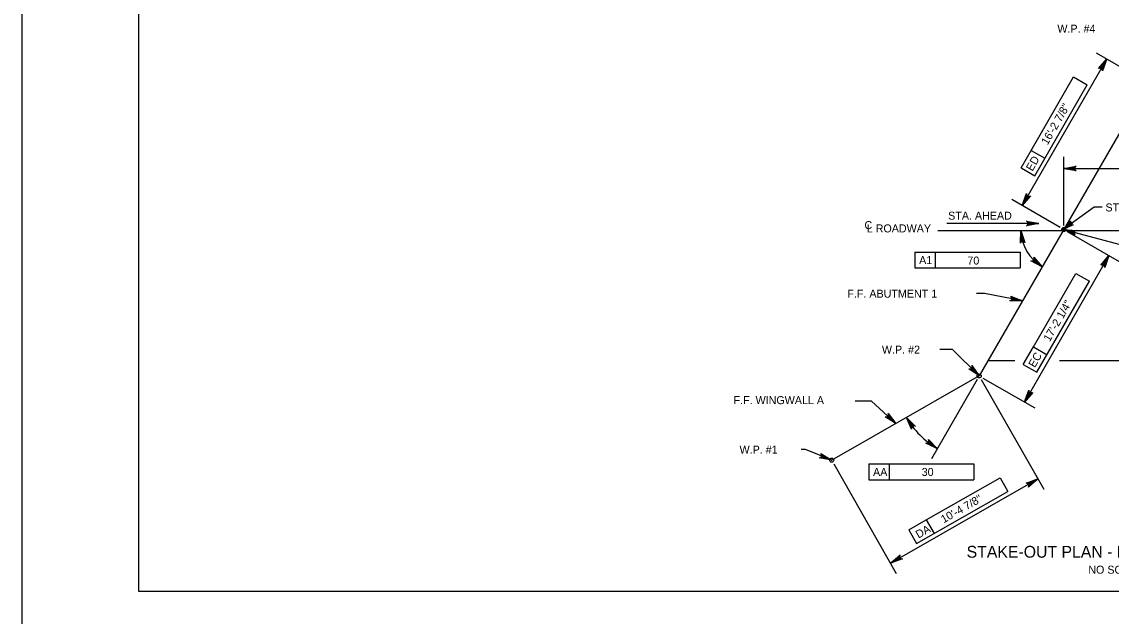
# Model space of a CAD drawing. Extents: x 179 to 454, y -271 to 54.
# Drawn here: x 209.75 to 226.08, y -87.62 to -78.72 of the extents above; entities that cross this region are included whole.
import ezdxf

# ---------------------------------------------------------------- set-up
doc = ezdxf.new("R2010")
doc.units = 0
for name, color, linetype in [('Level 1', 7, 'Continuous'), ('Level 2', 7, 'Continuous'), ('Level 3', 7, 'Continuous'), ('Level 4', 7, 'Continuous'), ('Level 41', 7, 'Continuous'), ('Level 5', 7, 'Continuous'), ('Level 63', 7, 'Continuous')]:
    doc.layers.add(name, color=color, linetype=linetype)

msp = doc.modelspace()

# ---------------------------------------------------------------- linework, layer by layer
at = {"layer": 'Level 1'}
msp.add_lwpolyline([(211.497, -87.25), (242.997, -87.25), (242.997, -66.75), (211.497, -66.75)], close=True, dxfattribs=at)
at = {"layer": 'Level 2'}
for p, q in [((226.635, -79.633), (224.1, -84.024)), ((224.232, -83.795), (224.633, -83.795)), ((225.306, -83.795), (230.928, -83.795)), ((224.1, -84.024), (221.889, -85.286))]:
    msp.add_line(p, q, dxfattribs=at)
at = {"layer": 'Level 3'}
msp.add_line((223.48, -81.844), (229.019, -81.844), dxfattribs=at)
for centre in [(225.368, -81.829), (224.1, -84.024), (221.889, -85.286)]:
    msp.add_circle(centre, 0.0304, dxfattribs=at)
at = {"layer": 'Level 4'}
for p, q in [((226.582, -79.603), (225.859, -79.185)), ((226.012, -79.274), (224.745, -81.469)), ((224.878, -80.643), (225.514, -79.541)), ((224.932, -81.023), (225.719, -79.659)), ((225.514, -79.541), (225.719, -79.659)), ((224.727, -80.904), (224.878, -80.643)), ((224.878, -80.643), (225.083, -80.761)), ((225.368, -81.767), (225.369, -80.739)), ((224.727, -80.904), (224.932, -81.023)), ((225.369, -80.916), (232.059, -80.916)), ((225.314, -81.798), (224.591, -81.38)), ((225.339, -81.84), (225.825, -81.492)), ((225.825, -81.492), (225.945, -81.492)), ((224.996, -81.737), (223.615, -81.737)), ((225.421, -81.859), (226.2, -82.309)), ((223.137, -82.17), (223.44, -82.17)), ((223.137, -82.17), (223.137, -82.406)), ((223.44, -82.17), (223.44, -82.406)), ((223.44, -82.17), (224.712, -82.17)), ((224.712, -82.17), (224.712, -82.406)), ((226.046, -82.221), (224.779, -84.416)), ((223.137, -82.406), (224.712, -82.406)), ((224.912, -83.589), (225.548, -82.487)), ((224.966, -83.969), (225.753, -82.605)), ((225.548, -82.487), (225.753, -82.605)), ((224.178, -82.791), (224.058, -82.791)), ((224.751, -82.897), (224.178, -82.791)), ((224.761, -83.851), (224.912, -83.589)), ((224.912, -83.589), (225.117, -83.707)), ((224.761, -83.851), (224.966, -83.969)), ((224.069, -84.077), (223.384, -85.264)), ((224.131, -84.077), (225.069, -85.721)), ((224.153, -84.055), (224.932, -84.504)), ((221.919, -85.339), (222.857, -86.983)), ((222.447, -85.343), (222.749, -85.343)), ((222.447, -85.343), (222.447, -85.579)), ((222.749, -85.343), (222.749, -85.579)), ((222.749, -85.343), (224.022, -85.343)), ((224.022, -85.343), (224.022, -85.579)), ((222.447, -85.579), (224.022, -85.579)), ((222.77, -86.829), (224.981, -85.567)), ((223.307, -86.18), (224.412, -85.55)), ((224.412, -85.55), (224.529, -85.755)), ((223.161, -86.535), (224.529, -85.755)), ((223.044, -86.33), (223.307, -86.18)), ((223.307, -86.18), (223.424, -86.385)), ((223.044, -86.33), (223.161, -86.535))]:
    msp.add_line(p, q, dxfattribs=at)
for points in [[(225.936, -79.366), (225.97, -79.386), (226.012, -79.274)], [(225.487, -80.897), (225.487, -80.936), (225.369, -80.916)], [(224.787, -81.357), (224.821, -81.377), (224.745, -81.469)], [(225.5, -81.749), (225.477, -81.717), (225.391, -81.803)], [(225.368, -81.829), (225.479, -81.869), (225.484, -81.85)], [(225.97, -82.313), (226.004, -82.333), (226.046, -82.221)], [(224.1, -84.024), (224.023, -83.934), (224.009, -83.948)], [(224.821, -84.304), (224.855, -84.323), (224.779, -84.416)], [(222.85, -84.737), (222.769, -84.651), (222.756, -84.665)], [(223.057, -84.756), (223.09, -84.735), (223.011, -84.646)], [(223.384, -85.03), (223.363, -85.063), (223.473, -85.11)], [(221.889, -85.286), (221.783, -85.233), (221.775, -85.251)], [(224.869, -85.609), (224.888, -85.643), (224.981, -85.567)], [(222.862, -86.754), (222.882, -86.788), (222.77, -86.829)]]:
    msp.add_lwpolyline(points, close=True, dxfattribs=at)
for points in [[(224.996, -81.737), (224.81, -81.772), (224.824, -81.762), (224.831, -81.75), (224.834, -81.737), (224.831, -81.725), (224.824, -81.712), (224.81, -81.703), (224.996, -81.737), (224.824, -81.712), (224.831, -81.725), (224.996, -81.737), (224.834, -81.737), (224.831, -81.75), (224.996, -81.737), (224.824, -81.762)], [(224.723, -81.843), (224.786, -82.022), (224.774, -82.009), (224.761, -82.004), (224.748, -82.004), (224.736, -82.008), (224.725, -82.017), (224.717, -82.033), (224.723, -81.843), (224.725, -82.017), (224.736, -82.008), (224.723, -81.843), (224.748, -82.004), (224.761, -82.004), (224.723, -81.843), (224.774, -82.009)], [(225.368, -81.829), (226.44, -82.114), (226.531, -82.114)], [(225.045, -82.387), (224.876, -82.301), (224.894, -82.302), (224.907, -82.296), (224.917, -82.287), (224.923, -82.276), (224.924, -82.262), (224.919, -82.245), (225.045, -82.387), (224.924, -82.262), (224.923, -82.276), (225.045, -82.387), (224.917, -82.287), (224.907, -82.296), (225.045, -82.387), (224.894, -82.302)], [(226.046, -82.221), (225.983, -82.399), (225.982, -82.382), (225.975, -82.369), (225.965, -82.361), (225.953, -82.357), (225.939, -82.357), (225.923, -82.364), (226.046, -82.221), (225.939, -82.357), (225.953, -82.357), (226.046, -82.221), (225.965, -82.361), (225.975, -82.369), (226.046, -82.221), (225.982, -82.382)], [(224.751, -82.897), (224.561, -82.897), (224.577, -82.89), (224.587, -82.879), (224.591, -82.867), (224.591, -82.855), (224.586, -82.841), (224.574, -82.829), (224.751, -82.897), (224.586, -82.841), (224.591, -82.855), (224.751, -82.897), (224.591, -82.867), (224.587, -82.879), (224.751, -82.897), (224.577, -82.89)], [(224.1, -84.024), (223.701, -83.63), (223.512, -83.63)], [(224.1, -84.024), (223.943, -83.918), (223.96, -83.921), (223.974, -83.917), (223.985, -83.91), (223.992, -83.899), (223.995, -83.885), (223.992, -83.868), (224.1, -84.024), (223.995, -83.885), (223.992, -83.899), (224.1, -84.024), (223.985, -83.91), (223.974, -83.917), (224.1, -84.024), (223.96, -83.921)], [(224.779, -84.416), (224.842, -84.237), (224.843, -84.254), (224.85, -84.267), (224.86, -84.275), (224.872, -84.279), (224.887, -84.279), (224.902, -84.272), (224.779, -84.416), (224.887, -84.279), (224.872, -84.279), (224.779, -84.416), (224.86, -84.275), (224.85, -84.267), (224.779, -84.416), (224.843, -84.254)], [(222.85, -84.737), (222.484, -84.404)], [(222.85, -84.737), (222.688, -84.638), (222.706, -84.64), (222.72, -84.636), (222.73, -84.628), (222.736, -84.617), (222.739, -84.603), (222.736, -84.586), (222.85, -84.737), (222.739, -84.603), (222.736, -84.617), (222.85, -84.737), (222.73, -84.628), (222.72, -84.636), (222.85, -84.737), (222.706, -84.64)], [(223.011, -84.646), (223.144, -84.78), (223.128, -84.774), (223.114, -84.775), (223.102, -84.78), (223.093, -84.789), (223.087, -84.802), (223.087, -84.82), (223.011, -84.646), (223.087, -84.802), (223.093, -84.789), (223.011, -84.646), (223.102, -84.78), (223.114, -84.775), (223.011, -84.646), (223.128, -84.774)], [(223.472, -85.112), (223.3, -85.032), (223.317, -85.033), (223.331, -85.027), (223.34, -85.018), (223.345, -85.006), (223.346, -84.992), (223.34, -84.975), (223.472, -85.112), (223.346, -84.992), (223.345, -85.006), (223.472, -85.112), (223.34, -85.018), (223.331, -85.027), (223.472, -85.112), (223.317, -85.033)], [(221.889, -85.286), (221.495, -85.129), (221.43, -85.129)], [(221.889, -85.286), (221.703, -85.249), (221.72, -85.245), (221.731, -85.237), (221.738, -85.226), (221.74, -85.213), (221.738, -85.199), (221.728, -85.184), (221.889, -85.286), (221.738, -85.199), (221.74, -85.213), (221.889, -85.286), (221.738, -85.226), (221.731, -85.237), (221.889, -85.286), (221.72, -85.245)], [(224.981, -85.567), (224.837, -85.69), (224.844, -85.674), (224.844, -85.66), (224.84, -85.648), (224.832, -85.638), (224.819, -85.631), (224.802, -85.629), (224.981, -85.567), (224.819, -85.631), (224.832, -85.638), (224.981, -85.567), (224.84, -85.648), (224.844, -85.66), (224.981, -85.567), (224.844, -85.674)], [(222.77, -86.829), (222.914, -86.707), (222.907, -86.722), (222.906, -86.737), (222.911, -86.749), (222.919, -86.759), (222.931, -86.766), (222.949, -86.767), (222.77, -86.829), (222.931, -86.766), (222.919, -86.759), (222.77, -86.829), (222.911, -86.749), (222.906, -86.737), (222.77, -86.829), (222.907, -86.722)]]:
    msp.add_lwpolyline(points, dxfattribs=at)
for centre, radius, start, end in [((225.368, -81.829), 0.644, 181.3505, 240), ((224.1, -84.024), 1.255, 209.7121, 239.9991)]:
    msp.add_arc(centre, radius, start, end, dxfattribs=at)
at = {"layer": 'Level 5'}
msp.add_line((222.484, -84.404), (222.243, -84.404), dxfattribs=at)
for points in [[(226.012, -79.274), (225.949, -79.453), (225.948, -79.435), (225.941, -79.423), (225.931, -79.415), (225.919, -79.41), (225.904, -79.41), (225.889, -79.418), (226.012, -79.274), (225.904, -79.41), (225.919, -79.41), (226.012, -79.274), (225.931, -79.415), (225.941, -79.423), (226.012, -79.274), (225.948, -79.435)], [(225.369, -80.916), (225.555, -80.882), (225.541, -80.891), (225.534, -80.904), (225.532, -80.916), (225.534, -80.929), (225.541, -80.941), (225.555, -80.951), (225.369, -80.916), (225.541, -80.941), (225.534, -80.929), (225.369, -80.916), (225.532, -80.916), (225.534, -80.904), (225.369, -80.916), (225.541, -80.891)], [(224.745, -81.469), (224.808, -81.29), (224.809, -81.308), (224.816, -81.32), (224.826, -81.328), (224.838, -81.333), (224.852, -81.333), (224.868, -81.325), (224.745, -81.469), (224.852, -81.333), (224.838, -81.333), (224.745, -81.469), (224.826, -81.328), (224.816, -81.32), (224.745, -81.469), (224.809, -81.308)], [(225.339, -81.84), (225.471, -81.703), (225.465, -81.719), (225.466, -81.734), (225.471, -81.745), (225.481, -81.754), (225.494, -81.76), (225.511, -81.76), (225.339, -81.84), (225.494, -81.76), (225.481, -81.754), (225.339, -81.84), (225.471, -81.745), (225.466, -81.734), (225.339, -81.84), (225.465, -81.719)], [(225.368, -81.829), (225.557, -81.843), (225.54, -81.849), (225.53, -81.859), (225.525, -81.87), (225.523, -81.883), (225.527, -81.897), (225.539, -81.91), (225.368, -81.829), (225.527, -81.897), (225.523, -81.883), (225.368, -81.829), (225.525, -81.87), (225.53, -81.859), (225.368, -81.829), (225.54, -81.849)]]:
    msp.add_lwpolyline(points, dxfattribs=at)
at = {"layer": 'Level 63'}
msp.add_lwpolyline([(209.747, -88), (243.747, -88), (243.747, -66), (209.747, -66)], close=True, dxfattribs=at)

# ---------------------------------------------------------------- texts
at = {"layer": 'Level 4'}
for s, height, p in [('W.P. #4', 0.12, (225.272, -78.88)), ('STA.', 0.12, (225.993, -81.559)), ('STA. AHEAD', 0.12, (223.635, -81.682)), ('C', 0.12, (222.38, -81.824)), ('L ROADWAY', 0.12, (222.415, -81.873)), ('A1', 0.12, (223.2, -82.348)), ('F.F. ABUTMENT 1', 0.12, (222.124, -82.851)), ('W.P. #2', 0.12, (222.642, -83.69)), ('F.F. WINGWALL A', 0.12, (220.418, -84.447)), ('W.P. #1', 0.12, (220.508, -85.189)), ('AA', 0.12, (222.509, -85.524)), ('STAKE-OUT PLAN - LEFT SKEW', 0.17717, (223.912, -86.748)), ('NO SCALE', 0.12, (225.736, -86.988))]:
    msp.add_text(s, height=height, dxfattribs=at).set_placement(p)
for s, rotation, p in [('ED', 60, (224.898, -80.965)), ('EC', 60, (224.934, -83.908)), ('DA', 29.7109, (223.19, -86.463))]:
    msp.add_text(s, height=0.12, rotation=rotation, dxfattribs=at).set_placement(p)
at = {"layer": 'Level 41'}
for s, rotation, p in [('16\'-2 7/8"', 60.0009, (225.125, -80.572)), ('17\'-2 1/4"', 60.0009, (225.157, -83.52)), ('10\'-4 7/8"', 29.7114, (223.568, -86.235))]:
    msp.add_text(s, height=0.12, rotation=rotation, dxfattribs=at).set_placement(p)
for s, p in [('70', (223.923, -82.355)), ('30', (223.238, -85.523))]:
    msp.add_text(s, height=0.12, dxfattribs=at).set_placement(p)

doc.saveas('drawing.dxf')
